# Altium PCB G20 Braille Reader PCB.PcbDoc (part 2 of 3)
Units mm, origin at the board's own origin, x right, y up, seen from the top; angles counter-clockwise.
Board outline 160.1 x 170.2 mm, 2 copper layers (Top Layer, Bottom Layer); 206 components, 272 nets, 975 pads, 345 vias.
Unrouted connection lines stored in the file: 1.
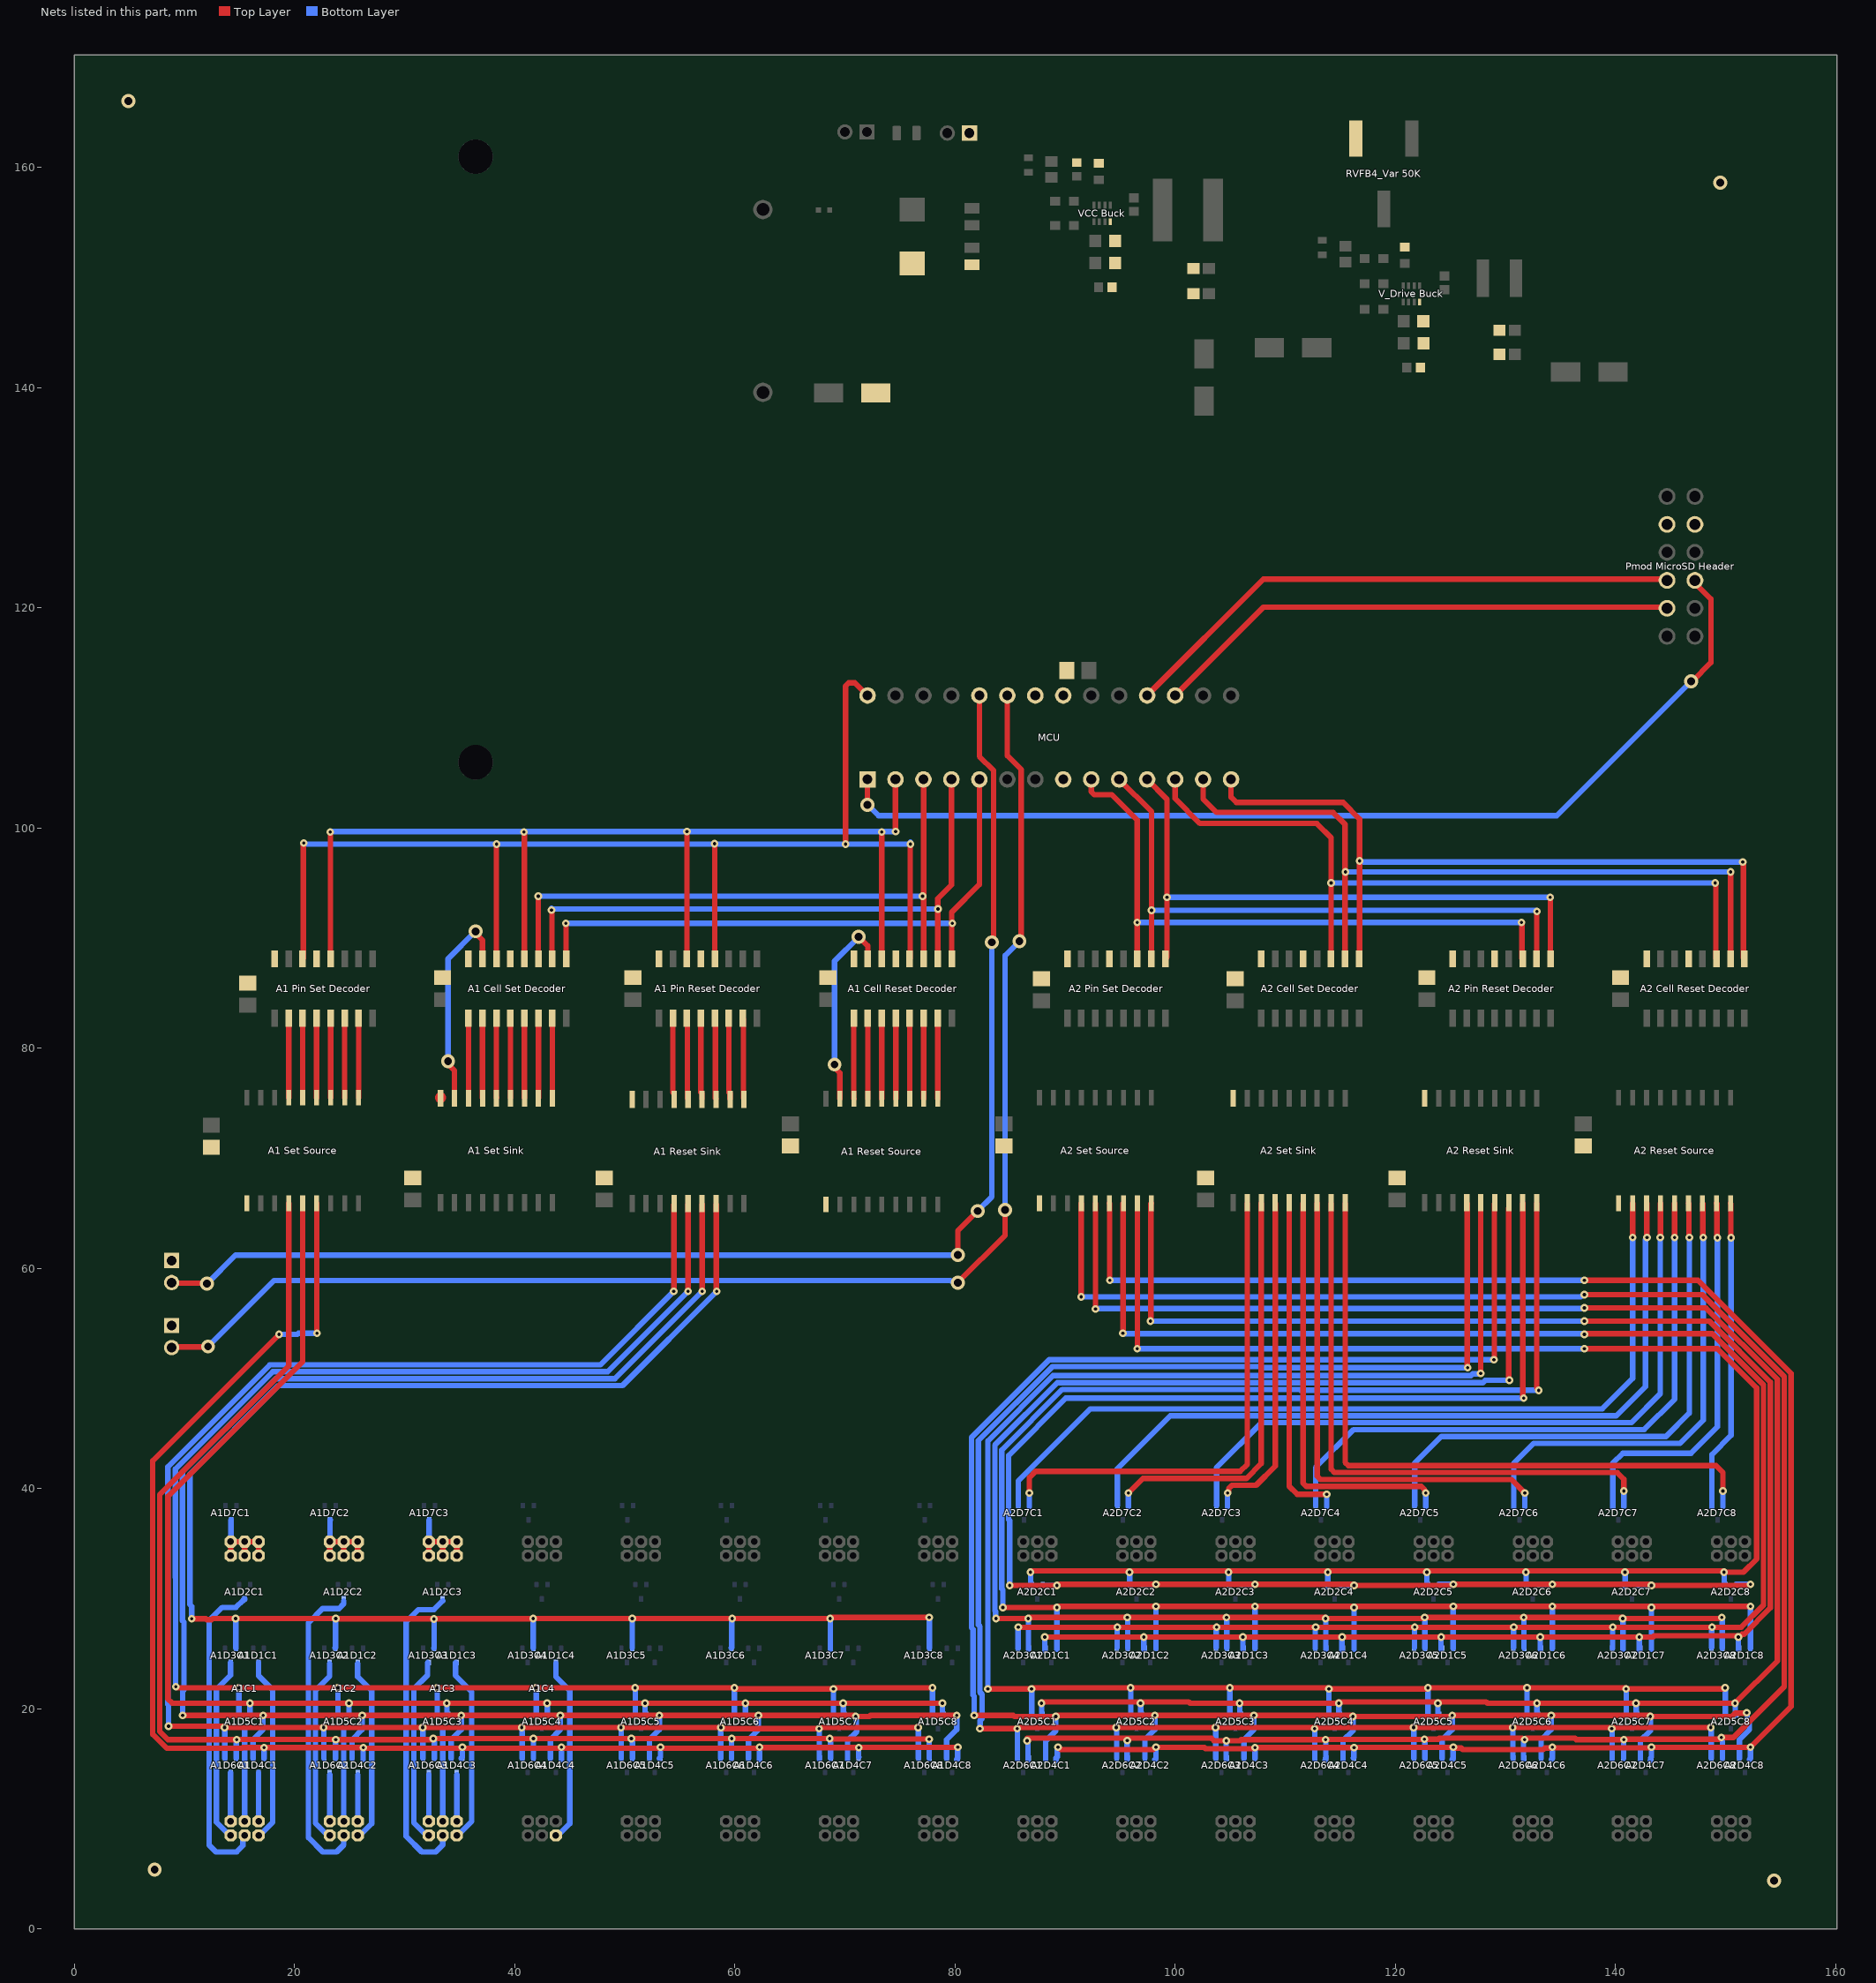
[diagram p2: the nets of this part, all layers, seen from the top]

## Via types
v1: diameter 0.7, hole 0.3, Top Layer to Bottom Layer, 308 vias
v2: diameter 1.27, hole 0.711, Top Layer to Bottom Layer, 37 vias

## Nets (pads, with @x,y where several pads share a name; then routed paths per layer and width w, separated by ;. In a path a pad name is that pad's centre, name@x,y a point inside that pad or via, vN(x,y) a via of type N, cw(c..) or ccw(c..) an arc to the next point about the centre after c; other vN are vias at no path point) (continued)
"A1 Pin3 Reset": "A1 Reset Sink.16" A1D3C1.2 A1D3C2.2 A1D3C3.2 A1D3C4.2 A1D3C5.2 A1D3C6.2 A1D3C7.2 A1D3C8.2 | length 164.7
  Top Layer w0.5: v1(10.673,28.174) 11.953,28.174 12.023,28.105 12.473,28.105 12.573,28.205 v1(14.646,28.205) v1(23.746,28.205) 23.767,28.184 32.65,28.184 v1(32.671,28.163) 32.687,28.18 41.654,28.18 v1(41.671,28.197) v1(50.671,28.197) 50.675,28.201 59.742,28.201 v1(59.746,28.205) 59.75,28.201 68.642,28.201 v1(68.646,28.197) 68.713,28.197 68.821,28.305 v1(77.646,28.305) ; 58.286,65.805 58.316,65.775 58.316,57.935 v1(58.346,57.905)
  Bottom Layer w0.5: v1(10.673,28.174) 10.673,29.298 10.5,29.471 10.5,41.314 18.54,49.354 49.795,49.354 v1(58.346,57.905) ; v1(14.646,28.205) 14.671,28.18 14.671,25.511 A1D3C1.2@14.695,25.487 ; A1D3C2.2@23.695,25.536 23.721,25.561 23.721,28.179 v1(23.746,28.205) ; A1D3C3.2@32.671,25.511 32.683,25.524 32.683,28.151 v1(32.671,28.163) ; A1D3C4.2@41.671,25.511 41.683,25.524 41.683,28.184 v1(41.671,28.197) ; A1D3C5.2@50.671,25.511 50.683,25.524 50.683,28.184 v1(50.671,28.197) ; A1D3C6.2@59.683,25.524 59.721,25.561 59.721,28.179 v1(59.746,28.205) ; v1(68.646,28.197) 68.671,28.172 A1D3C7.2@68.671,25.411 ; A1D3C8.2@77.671,25.511 v1@77.671,28.28
"A1 Pin4": "A1 Set Source.15" A1D4C1.2 A1D4C2.2 A1D4C3.2 A1D4C4.2 A1D4C5.2 A1D4C6.2 A1D4C7.2 A1D4C8.2 | length 138.1
  Top Layer w0.5: v1(17.246,16.479) 15.311,16.479 15.237,16.405 8.409,16.405 7.127,17.686 7.127,42.527 v1(18.6,54) ; v1@17.283,16.442 17.319,16.478 v1(26.246,16.478) ; 22.016,65.905 22.031,65.89 22.031,54.119 v1(22.045,54.105) ; v1@26.246,16.405 35.246,16.405 44.246,16.405 53.246,16.405 62.246,16.405 62.319,16.478 71.223,16.478 v1@71.246,16.455 ; v1@71.246,16.505 v1(80.246,16.505)
  Bottom Layer w0.5: A1D4C1.2@17.241,15.492 17.241,16.473 v1(17.246,16.479) ; v1(18.6,54) 20.251,54 20.356,54.105 v1(22.045,54.105) ; A1D4C2.2@26.241,15.392 26.241,16.472 v1(26.246,16.478) ; A1D4C3.2@35.13,15.494 35.246,15.61 35.241,15.616 35.241,16.399 v1@35.246,16.405 ; A1D4C4.2@44.241,15.392 44.241,16.399 v1@44.246,16.405 ; A1D4C5.2@53.13,15.494 53.246,15.61 53.241,15.616 53.241,16.399 v1@53.246,16.405 ; A1D4C6.2@62.241,15.392 62.241,16.399 v1@62.246,16.405 ; A1D4C7.2@71.246,15.61 71.241,15.616 71.241,16.385 71.246,16.391 v1(71.246,16.478) ; A1D4C8.2@80.141,15.392 80.246,15.498 80.241,15.503 80.241,16.499 v1(80.246,16.505)
  other v1: 35.246,16.505 44.246,16.505 53.246,16.505 62.246,16.505
"A1 Pin4 Reset": "A1 Reset Sink.15" A1D4C1.1 A1D4C2.1 A1D4C3.1 A1D4C4.1 A1D4C5.1 A1D4C6.1 A1D4C7.1 A1D4C8.1 | length 188.9
  Top Layer w0.5: v1(9.846,19.405) v1(35.146,19.405) v1(44.146,19.405) v1(53.146,19.405) 70.819,19.405 70.919,19.305 72.223,19.305 72.323,19.405 v1(80.146,19.405) ; 57.016,65.805 57.024,65.797 57.024,57.913 v1(57.032,57.905)
  Bottom Layer w0.5: v1(9.846,19.405) 9.846,21.596 9.954,21.704 9.954,27.865 9.819,28 9.819,41.519 18.281,49.981 49.108,49.981 v1(57.032,57.905) ; A1D4C1.1@16.235,15.487 16.235,17.194 17.146,18.105 v1(17.146,19.405) ; A1D4C2.1@25.235,15.487 25.235,17.194 26.146,18.105 v1(26.146,19.405) ; A1D4C3.1@34.235,15.487 34.235,17.194 35.146,18.105 v1(35.146,19.405) ; A1D4C4.1@43.235,15.487 43.235,17.194 44.146,18.105 v1(44.146,19.405) ; A1D4C5.1@52.235,15.487 52.235,17.194 53.146,18.105 v1(53.146,19.405) ; A1D4C6.1@61.235,15.487 61.235,17.194 62.146,18.105 v1(62.146,19.405) ; A1D4C7.1@70.235,15.387 70.235,17.094 71.073,17.932 71.073,18.346 71.011,18.408 71.011,19.266 v1(70.973,19.305) ; A1D4C8.1@79.235,15.487 79.235,17.194 80.146,18.105 v1(80.146,19.405)
"A1 Pin5": "A1 Set Source.14" A1D5C1.2 A1D5C2.2 A1D5C3.2 A1D5C4.2 A1D5C5.2 A1D5C6.2 A1D5C7.2 A1D5C8.2 | length 128.6
  Top Layer w0.5: 20.746,65.905 20.746,51.533 8.5,39.287 8.5,20.9 8.895,20.505 v1(15.946,20.505) v1(24.946,20.505) ; v1(24.946,20.505) v1@33.834,20.506 ; v1(33.835,20.506) v1@42.945,20.506 ; v1(42.946,20.505) v1(51.835,20.505) v1(60.946,20.505) v1(69.835,20.505) v1(78.846,20.505)
  Bottom Layer w0.5: v1(15.946,20.505) 15.956,20.495 15.956,19.496 A1D5C1.2@15.965,19.487 ; A1D5C2.2@24.956,19.396 v1@24.956,20.395 ; A1D5C3.2@33.845,19.498 v1@33.845,20.497 ; A1D5C4.2@42.956,19.396 v1@42.956,20.395 ; A1D5C5.2@51.845,19.498 v1@51.845,20.497 ; A1D5C6.2@60.956,19.396 v1@60.956,20.395 ; A1D5C7.2@69.845,19.498 v1@69.845,20.497 ; A1D5C8.2@78.856,19.396 v1@78.856,20.395
"A1 Pin5 Reset": "A1 Reset Sink.14" A1D5C1.1 A1D5C2.1 A1D5C3.1 A1D5C4.1 A1D5C5.1 A1D5C6.1 A1D5C7.1 A1D5C8.1 | length 169
  Top Layer w0.5: v1(9.227,22.005) 9.281,22.005 9.381,21.905 v1(23.946,21.905) v1(32.946,21.905) v1(41.946,21.905) v1(50.946,21.905) v1(59.946,21.905) 60.013,21.905 60.113,21.805 v1(68.946,21.805) 69.013,21.805 69.113,21.905 v1(77.946,21.905) ; v1(55.746,57.905) 55.746,65.805
  Bottom Layer w0.5: v1(9.227,22.005) 9.192,22.04 9.192,31.928 9.184,31.936 9.184,41.771 18.021,50.608 48.449,50.608 v1(55.746,57.905) ; v1(14.946,21.905) 14.956,21.895 14.956,19.496 A1D5C1.1@14.965,19.487 ; A1D5C2.1@23.956,19.496 v1@23.956,21.895 ; A1D5C3.1@32.956,19.496 v1@32.956,21.895 ; A1D5C4.1@41.956,19.496 v1@41.956,21.895 ; A1D5C5.1@50.956,19.496 v1@50.956,21.895 ; A1D5C6.1@59.956,19.496 v1@59.956,21.895 ; A1D5C7.1@68.956,19.396 v1@68.956,21.795 ; A1D5C8.1@77.956,19.496 v1@77.956,21.895
"A1 Pin6": "A1 Set Source.13" A1D6C1.2 A1D6C2.2 A1D6C3.2 A1D6C4.2 A1D6C5.2 A1D6C6.2 A1D6C7.2 A1D6C8.2 | length 137.3
  Top Layer w0.5: 19.476,65.905 19.476,51.149 7.754,39.427 7.754,17.946 8.495,17.205 v1(14.743,17.206) v1(14.743,17.206) v1(23.743,17.205) v1(23.743,17.205) 32.451,17.205 32.546,17.3 v1(68.6,17.3) 68.634,17.266 77.558,17.266 v1@77.619,17.205
  Bottom Layer w0.5: A1D6C1.2@14.719,15.51 14.719,17.182 v1(14.743,17.206) ; A1D6C2.2@23.719,15.51 23.719,17.181 v1(23.743,17.205) ; v1(32.6,17.3) 32.6,17.246 32.695,17.151 A1D6C3.2@32.695,15.51 ; A1D6C4.2@41.702,15.51 41.702,17.294 v1(41.708,17.3) ; v1(50.6,17.3) 50.6,17.246 50.695,17.151 A1D6C5.2@50.695,15.51 ; A1D6C6.2@59.702,15.51 59.702,17.294 v1(59.708,17.3) ; v1(68.6,17.3) 68.6,17.246 68.695,17.151 A1D6C7.2@68.695,15.51 ; A1D6C8.2@77.646,15.51 v1(77.646,17.232)
"A1 Pin6 Reset": "A1 Reset Sink.13" A1D6C1.1 A1D6C2.1 A1D6C3.1 A1D6C4.1 A1D6C5.1 A1D6C6.1 A1D6C7.1 A1D6C8.1 | length 174.5
  Top Layer w0.5: v1(8.551,18.41) 13.474,18.41 13.58,18.305 v1(22.646,18.305) v1(31.646,18.305) v1(40.646,18.305) v1(49.646,18.305) 58.781,18.305 58.881,18.205 v1(67.646,18.205) 67.693,18.252 67.865,18.252 67.918,18.305 v1(76.646,18.305) ; v1(54.446,57.905) 54.461,57.92 54.461,65.79 54.476,65.805
  Bottom Layer w0.5: v1(8.551,18.41) 8.551,20.359 8.5,20.411 8.5,41.974 17.761,51.235 47.776,51.235 v1(54.446,57.905) ; v1(13.646,18.305) 13.671,18.28 13.671,15.511 A1D6C1.1@13.695,15.487 ; A1D6C2.1@22.671,15.511 v1@22.671,18.28 ; A1D6C3.1@31.671,15.511 v1@31.671,18.28 ; A1D6C4.1@40.671,15.511 v1@40.671,18.28 ; A1D6C5.1@49.671,15.511 v1@49.671,18.28 ; A1D6C6.1@58.711,15.51 58.711,18.289 v1(58.727,18.305) ; A1D6C7.1@67.671,15.411 v1@67.671,18.18 ; A1D6C8.1@76.671,15.511 v1@76.671,18.28
"A2 Cell1": "A2 Set Sink.11" A2D7C1.2 | length 46.7
  Top Layer w0.5: v1(86.746,39.605) 86.746,40.997 87.303,41.554 105.895,41.554 106.546,42.205 106.546,59.295 106.536,59.305 106.536,65.905
  Bottom Layer w0.5: A2D7C1.2@86.746,38.35 v1(86.746,39.605)
"A2 Cell1 Reset": "A2 Reset Source.11" A2D7C1.1 | length 77.8
  Top Layer w0.5: 141.536,65.905 141.541,65.9 141.541,62.81 v1(141.546,62.805)
  Bottom Layer w0.5: A2D7C1.1@85.746,38.45 85.746,40.705 92.276,47.235 138.776,47.235 141.541,50 141.541,62.8 v1(141.546,62.805)
"A2 Cell2": "A2 Set Sink.12" A2D7C2.2 | length 38.1
  Top Layer w0.5: v1(95.746,39.605) 97.068,40.927 106.468,40.927 107.806,42.265 107.806,65.905
  Bottom Layer w0.5: A2D7C2.2@95.746,38.35 v1(95.746,39.605)
"A2 Cell2 Reset": "A2 Reset Source.12" A2D7C2.1 | length 71.1
  Top Layer w0.5: 142.806,65.905 142.826,65.885 142.826,62.825 v1(142.846,62.805)
  Bottom Layer w0.5: A2D7C2.1@94.746,38.45 94.746,41.805 99.549,46.608 140.049,46.608 142.7,49.259 142.7,62.605 142.846,62.751 v1(142.846,62.805)
"A2 Cell3": "A2 Set Sink.13" A2D7C3.2 | length 30.6
  Top Layer w0.5: v1@104.793,39.652 104.784,39.661 104.784,39.697 104.846,39.759 104.846,40.007 105.139,40.3 107.341,40.3 109.076,42.035 109.076,65.905
  Bottom Layer w0.5: A2D7C3.2@104.746,38.35 v1(104.746,39.605)
"A2 Cell3 Reset": "A2 Reset Source.13" A2D7C3.1 | length 63.8
  Top Layer w0.5: v1(144.046,62.805) 144.061,62.82 144.061,65.89 144.076,65.905
  Bottom Layer w0.5: A2D7C3.1@103.746,38.455 103.746,41.905 107.822,45.981 141.422,45.981 144.046,48.605 v1(144.046,62.805)
"A2 Cell4": "A2 Set Sink.14" A2D7C4.2 | length 30.5
  Top Layer w0.5: 110.346,65.905 110.346,40.205 111.078,39.473 v1(113.746,39.473)
  Bottom Layer w0.5: A2D7C4.2@113.746,38.35 v1(113.746,39.473)
"A2 Cell4 Reset": "A2 Reset Source.14" A2D7C4.1 | length 56.4
  Top Layer w0.5: v1(145.346,62.805) 145.346,65.905
  Bottom Layer w0.5: A2D7C4.1@112.746,38.45 112.746,41.905 116.195,45.354 142.595,45.354 145.346,48.105 v1(145.346,62.805)
"A2 Cell5": "A2 Set Sink.15" A2D7C5.2 | length 38.2
  Top Layer w0.5: 111.616,65.905 111.616,40.493 111.909,40.2 122.353,40.2 122.646,39.907 122.646,39.759 122.708,39.697 122.708,39.661 v1@122.699,39.652
  Bottom Layer w0.5: A2D7C5.2@122.746,38.35 v1(122.746,39.605)
"A2 Cell5 Reset": "A2 Reset Source.15" A2D7C5.1 | length 49.8
  Top Layer w0.5: 146.616,65.905 146.652,65.869 146.652,62.84 v1(146.687,62.805)
  Bottom Layer w0.5: A2D7C5.1@121.746,38.45 121.746,42.305 124.168,44.727 144.568,44.727 146.687,46.846 v1(146.687,62.805)
"A2 Cell6": "A2 Set Sink.16" A2D7C6.2 | length 45.5
  Top Layer w0.5: 112.886,65.905 112.886,41.12 113.179,40.827 130.524,40.827 v1(131.746,39.605)
  Bottom Layer w0.5: A2D7C6.2@131.746,38.35 v1(131.746,39.605)
"A2 Cell6 Reset": "A2 Reset Source.16" A2D7C6.1 | length 42.6
  Top Layer w0.5: 147.886,65.905 147.916,65.875 147.916,62.835 v1(147.946,62.805)
  Bottom Layer w0.5: A2D7C6.1@130.746,38.25 A2D7C6.1@130.746,38.45 130.746,42.305 132.541,44.1 145.841,44.1 147.946,46.205 v1(147.946,62.805)
"A2 Cell7": "A2 Set Sink.17" A2D7C7.2 | length 53.6
  Top Layer w0.5: 114.156,65.905 114.156,41.747 114.449,41.454 140.148,41.454 140.746,40.856 v1(140.746,39.774)
  Bottom Layer w0.5: A2D7C7.2@140.746,38.35 v1(140.746,39.774)
"A2 Cell7 Reset": "A2 Reset Source.17" A2D7C7.1 | length 35.3
  Top Layer w0.5: 149.156,65.905 149.201,65.86 149.201,62.819 v1(149.246,62.774)
  Bottom Layer w0.5: A2D7C7.1@139.746,38.25 A2D7C7.1@139.746,38.45 139.746,42.305 140.646,43.205 146.846,43.205 149.246,45.605 v1(149.246,62.774)
"A2 Cell8": "A2 Set Sink.18" A2D7C8.2 | length 61.3
  Top Layer w0.5: 115.426,65.905 115.426,42.374 115.719,42.081 149.121,42.081 149.746,41.456 v1(149.746,39.774)
  Bottom Layer w0.5: A2D7C8.2@149.746,38.35 v1(149.746,39.774)
"A2 Cell8 Reset": "A2 Reset Source.18" A2D7C8.1 | length 28.4
  Top Layer w0.5: 150.426,65.905 150.457,65.874 150.457,62.804 v1(150.487,62.774)
  Bottom Layer w0.5: A2D7C8.1@148.746,38.25 A2D7C8.1@148.746,38.45 148.746,43.096 150.487,44.837 v1(150.487,62.774)
"A2 Cell Select 0": "A2 Cell Reset Decoder.1" "A2 Cell Set Decoder.1" MCU.14 | length 70.5
  Top Layer w0.5: MCU.14@105.066,104.405 105.066,102.785 105.546,102.305 115.246,102.305 116.746,100.805 v1(116.746,97.005) 116.746,88.16 116.691,88.105 ; v1(151.546,96.905) 151.593,96.858 151.593,88.208 151.696,88.105
  Bottom Layer w0.5: v1(116.746,97.005) 116.8,97.005 116.9,96.905 v1(151.546,96.905)
"A2 Cell Select 1": "A2 Cell Reset Decoder.2" "A2 Cell Set Decoder.2" MCU.13 | length 70.8
  Top Layer w0.5: MCU.13@102.526,104.405 102.526,102.625 103.746,101.405 114.346,101.405 115.421,100.33 115.421,88.105 ; 150.426,88.105 150.436,88.115 150.436,95.995 v1(150.446,96.005)
  Bottom Layer w0.5: v1(115.446,96.005) v1(150.446,96.005)
"A2 Cell Select 2": "A2 Cell Reset Decoder.3" "A2 Cell Set Decoder.3" MCU.12 | length 70.2
  Top Layer w0.5: MCU.12@99.986,104.405 99.986,102.665 102.246,100.405 112.846,100.405 114.151,99.1 114.151,88.105 ; v1(149.046,95.005) 149.093,94.958 149.093,88.168 149.156,88.105
  Bottom Layer w0.5: v1(114.146,95.005) v1(149.046,95.005)
"A2 Pin1": "A2 Set Source.18" A2D1C1.1 A2D1C2.1 A2D1C3.1 A2D1C4.1 A2D1C5.1 A2D1C6.1 A2D1C7.1 A2D1C8.1 | length 165.3
  Top Layer w0.5: v1@88.213,26.528 88.236,26.505 97.054,26.505 97.146,26.597 97.238,26.505 106.19,26.505 106.233,26.548 106.233,26.51 106.238,26.505 115.19,26.505 115.233,26.548 115.233,26.51 115.238,26.505 124.054,26.505 124.146,26.597 124.238,26.505 133.19,26.505 133.233,26.548 133.233,26.51 133.238,26.505 142.19,26.505 142.233,26.548 142.233,26.51 142.238,26.505 143.373,26.505 143.496,26.628 v1@151.146,26.628 ; v1(97.746,55.205) 97.786,55.245 97.786,65.865 97.826,65.905 ; v1(137.146,55.205) 148.519,55.205 154.054,49.67 154.054,29.167 151.664,26.778 151.473,26.778 151.2,26.505 v1(151.146,26.505)
  Bottom Layer w0.5: A2D1C1.1@88.141,25.292 v1@88.141,26.299 ; A2D1C2.1@97.141,25.392 v1@97.141,26.399 ; v1(97.746,55.205) v1(137.146,55.205) ; A2D1C3.1@106.141,25.392 v1@106.141,26.399 ; A2D1C4.1@115.141,25.292 v1@115.141,26.299 ; A2D1C5.1@124.141,25.392 v1@124.141,26.399 ; A2D1C6.1@133.141,25.392 v1@133.141,26.399 ; A2D1C7.1@142.141,25.292 v1@142.141,26.299 ; A2D1C8.1@151.141,25.392 v1@151.141,26.399
  other v1: 88.146,26.505 97.146,26.505 106.146,26.505 115.146,26.505 124.146,26.505 133.146,26.505 142.146,26.505
"A2 Pin1 Reset": "A2 Reset Sink.18" A2D1C1.2 A2D1C2.2 A2D1C3.2 A2D1C4.2 A2D1C5.2 A2D1C6.2 A2D1C7.2 A2D1C8.2 | length 180.9
  Top Layer w0.5: v1@84.335,29.205 89.312,29.205 89.413,29.305 v1(98.246,29.305) v1(107.246,29.305) 116.246,29.305 v1(125.246,29.305) v1(134.246,29.305) 143.246,29.305 v1(152.246,29.305) ; 132.826,65.905 132.826,49.15 133.005,48.971 v1(133.005,48.905)
  Bottom Layer w0.5: v1(84.335,29.205) 84.335,30.804 84.235,30.904 84.235,43.494 89.738,48.997 111.298,48.997 111.363,48.932 132.978,48.932 v1(133.005,48.905) ; A2D1C1.2@89.241,25.392 v1@89.241,29.199 ; A2D1C2.2@98.241,25.492 v1@98.241,29.299 ; A2D1C3.2@107.241,25.492 v1@107.241,29.299 ; A2D1C4.2@116.241,25.392 v1@116.241,29.199 ; A2D1C5.2@125.241,25.492 v1@125.241,29.299 ; A2D1C6.2@134.241,25.492 v1@134.241,29.299 ; A2D1C7.2@143.241,25.392 v1@143.241,29.199 ; A2D1C8.2@152.241,25.492 v1@152.241,29.299
  other v1: 89.246,29.205 116.246,29.205 143.246,29.205
"A2 Pin2": "A2 Set Source.17" A2D2C1.1 A2D2C2.1 A2D2C3.1 A2D2C4.1 A2D2C5.1 A2D2C6.1 A2D2C7.1 A2D2C8.1 | length 162
  Top Layer w0.5: v1@86.846,32.528 v1@95.68,32.528 ; v1@95.68,32.428 95.78,32.528 113.68,32.528 v1@113.78,32.428 ; v1(96.546,52.705) 96.551,52.71 96.551,65.9 96.556,65.905 ; v1@113.78,32.528 v1@122.68,32.528 ; v1@122.68,32.428 122.78,32.528 140.68,32.528 v1@140.78,32.428 ; v1(137.146,52.705) 149.246,52.705 152.8,49.151 152.8,33.597 151.608,32.405 v1(149.846,32.405) ; v1@140.78,32.528 v1@149.68,32.528 ; v1@149.68,32.428 149.78,32.528 v1@149.846,32.528
  Bottom Layer w0.5: A2D2C1.1@86.856,31.093 v1@86.856,32.195 ; A2D2C2.1@95.856,31.193 v1@95.856,32.295 ; v1(96.546,52.705) v1(137.146,52.705) ; A2D2C3.1@104.856,31.193 v1@104.856,32.295 ; A2D2C4.1@113.856,31.093 v1@113.856,32.195 ; A2D2C5.1@122.856,31.193 v1@122.856,32.295 ; A2D2C6.1@131.856,31.193 v1@131.856,32.295 ; A2D2C7.1@140.856,31.093 v1@140.856,32.195 ; A2D2C8.1@149.856,31.193 v1@149.856,32.295
  other v1: 86.846,32.405 95.846,32.405 104.846,32.405 113.846,32.405 122.846,32.405 131.846,32.405 140.846,32.405
"A2 Pin2 Reset": "A2 Reset Sink.17" A2D2C1.2 A2D2C2.2 A2D2C3.2 A2D2C4.2 A2D2C5.2 A2D2C6.2 A2D2C7.2 A2D2C8.2 | length 156.2
  Top Layer w0.5: v1(84.962,31.205) 89.313,31.205 89.413,31.305 v1(98.246,31.305) 116.092,31.305 116.154,31.243 116.192,31.243 116.246,31.297 116.338,31.205 125.092,31.205 125.192,31.305 143.092,31.305 143.154,31.243 143.192,31.243 143.246,31.297 143.338,31.205 152.092,31.205 152.192,31.305 v1(152.246,31.305) ; 131.556,65.905 131.556,48.361 131.646,48.271 v1(131.646,48.205)
  Bottom Layer w0.5: v1(84.962,31.205) 84.962,37.09 84.862,37.19 84.862,43.021 90.046,48.205 v1(131.646,48.205) ; A2D2C1.2@87.976,31.194 v1@89.236,31.194 ; A2D2C2.2@96.976,31.294 v1@98.236,31.294 ; A2D2C3.2@105.976,31.294 v1@107.236,31.294 ; A2D2C4.2@114.976,31.194 v1@116.236,31.194 ; A2D2C5.2@123.976,31.294 v1@125.236,31.294 ; A2D2C6.2@132.976,31.294 v1@134.236,31.294 ; A2D2C7.2@141.976,31.194 v1@143.236,31.194 ; A2D2C8.2@150.976,31.294 v1@152.236,31.294
  other v1: 89.246,31.205 116.246,31.205 143.246,31.205 107.246,31.305 125.246,31.305 134.246,31.305
"A2 Pin3": "A2 Set Source.16" A2D3C1.1 A2D3C2.1 A2D3C3.1 A2D3C4.1 A2D3C5.1 A2D3C6.1 A2D3C7.1 A2D3C8.1 | length 175.3
  Top Layer w0.5: v1(85.746,27.405) 94.654,27.405 94.708,27.459 94.708,27.497 94.8,27.405 103.654,27.405 103.746,27.497 103.838,27.405 112.657,27.405 v1@112.68,27.428 ; v1(95.246,54.105) 95.266,54.125 95.266,65.885 95.286,65.905 ; v1(112.746,27.405) 121.654,27.405 121.746,27.497 121.838,27.405 130.654,27.405 130.746,27.497 130.838,27.405 139.657,27.405 v1@139.68,27.428 ; v1(137.146,54.005) 137.205,54.063 148.774,54.063 153.427,49.411 153.427,29.427 151.405,27.405 v1(148.746,27.405) ; v1(139.746,27.405) 148.654,27.405 v1@148.746,27.497
  Bottom Layer w0.5: A2D3C1.1@85.721,25.463 v1@85.721,27.279 ; A2D3C2.1@94.721,25.563 v1@94.721,27.379 ; v1(95.246,54.105) 95.296,54.055 137.096,54.055 v1(137.146,54.005) ; A2D3C3.1@103.721,25.563 v1@103.721,27.379 ; A2D3C4.1@112.721,25.463 v1@112.721,27.279 ; A2D3C5.1@121.721,25.563 v1@121.721,27.379 ; A2D3C6.1@130.721,25.563 v1@130.721,27.379 ; A2D3C7.1@139.721,25.463 v1@139.721,27.279 ; A2D3C8.1@148.721,25.563 v1@148.721,27.379
  other v1: 94.746,27.405 103.746,27.405 121.746,27.405 130.746,27.405
"A2 Pin3 Reset": "A2 Reset Sink.16" A2D3C1.2 A2D3C2.2 A2D3C3.2 A2D3C4.2 A2D3C5.2 A2D3C6.2 A2D3C7.2 A2D3C8.2 | length 169
  Top Layer w0.5: v1(83.708,28.205) 86.713,28.205 86.813,28.305 v1(95.646,28.305) 113.492,28.305 113.554,28.243 113.592,28.243 113.646,28.297 113.738,28.205 122.492,28.205 122.592,28.305 140.492,28.305 140.554,28.243 140.592,28.243 140.646,28.297 140.738,28.205 149.492,28.205 149.592,28.305 v1(149.646,28.305) ; 130.286,65.437 130.286,49.941 130.346,49.881 v1(130.346,49.827)
  Bottom Layer w0.5: v1(83.708,28.205) 83.67,28.243 83.67,28.843 83.608,28.904 83.608,43.944 89.288,49.624 127.944,49.624 128.147,49.827 v1(130.346,49.827) ; A2D3C1.2@86.671,25.411 v1@86.671,28.18 ; A2D3C2.2@95.671,25.511 v1@95.671,28.28 ; A2D3C3.2@104.671,25.511 v1@104.671,28.28 ; A2D3C4.2@113.671,25.411 v1@113.671,28.18 ; A2D3C5.2@122.671,25.511 v1@122.671,28.28 ; A2D3C6.2@131.671,25.511 v1@131.671,28.28 ; A2D3C7.2@140.671,25.411 v1@140.671,28.18 ; A2D3C8.2@149.671,25.511 v1@149.671,28.28
  other v1: 86.646,28.205 113.646,28.205 140.646,28.205 104.646,28.305 122.646,28.305 131.646,28.305
"A2 Pin4": "A2 Set Source.15" A2D4C1.2 A2D4C2.2 A2D4C3.2 A2D4C4.2 A2D4C5.2 A2D4C6.2 A2D4C7.2 A2D4C8.2 | length 180.4
  Top Layer w0.5: v1(89.346,16.505) 89.4,16.505 89.605,16.3 97.987,16.3 98.192,16.505 102.633,16.505 102.76,16.378 107.092,16.378 107.192,16.478 v1(116.246,16.478) ; 94.016,65.905 94.031,65.89 94.031,58.92 v1(94.046,58.905) ; v1@116.273,16.505 v1(125.246,16.505) 125.319,16.432 125.977,16.432 126.104,16.305 133.438,16.305 133.572,16.439 134.18,16.439 v1(134.246,16.505) 134.3,16.451 143.192,16.451 v1(143.246,16.505) v1(152.246,16.505) 155.935,20.194 155.935,50.449 147.48,58.905 v1(137.146,58.905)
  Bottom Layer w0.5: A2D4C1.2@89.141,15.292 89.162,15.314 89.162,15.526 89.246,15.61 89.268,15.61 89.291,15.633 89.291,16.449 v1(89.346,16.505) ; v1(94.046,58.905) v1(137.146,58.905) ; A2D4C2.2@98.141,15.392 98.246,15.498 98.241,15.503 98.241,16.499 v1(98.246,16.505) ; A2D4C3.2@107.241,15.51 107.241,16.472 v1(107.246,16.478) ; A2D4C4.2@116.162,15.526 116.208,15.572 116.208,16.439 v1(116.246,16.478) ; A2D4C5.2@125.141,15.392 125.246,15.498 125.241,15.503 125.241,16.499 v1(125.246,16.505) ; A2D4C6.2@134.141,15.392 134.246,15.498 134.241,15.503 134.241,16.499 v1(134.246,16.505) ; A2D4C7.2@143.141,15.292 143.162,15.314 143.162,15.526 143.246,15.61 143.241,15.616 143.241,16.499 v1(143.246,16.505) ; A2D4C8.2@152.141,15.392 152.246,15.498 152.241,15.503 152.241,16.499 v1(152.246,16.505)
"A2 Pin4 Reset": "A2 Reset Sink.15" A2D4C1.1 A2D4C2.1 A2D4C3.1 A2D4C4.1 A2D4C5.1 A2D4C6.1 A2D4C7.1 A2D4C8.1 | length 195.2
  Top Layer w0.5: v1(81.727,19.405) 85.273,19.405 85.373,19.305 89.213,19.305 89.313,19.405 v1(98.146,19.405) v1(107.146,19.405) 115.98,19.405 116.032,19.352 116.093,19.352 116.146,19.405 116.16,19.405 116.26,19.305 124.98,19.305 125.08,19.405 v1(134.146,19.405) 142.98,19.405 143.032,19.352 143.093,19.352 143.146,19.405 143.16,19.405 143.26,19.305 150.561,19.305 150.858,19.601 151.873,19.601 v1(151.911,19.639) ; v1(128.946,51.705) 128.981,51.74 128.981,65.87 129.016,65.905
  Bottom Layer w0.5: v1(81.727,19.405) 81.727,21.144 81.627,21.244 81.627,27.222 81.492,27.357 81.492,44.651 88.546,51.705 v1(128.946,51.705) ; A2D4C1.1@88.235,15.387 88.235,17.094 89.146,18.005 v1(89.146,19.305) ; A2D4C2.1@97.235,15.487 A2D4C2.1@97.235,15.505 97.235,17.194 98.146,18.105 v1(98.146,19.405) ; A2D4C3.1@106.235,15.487 A2D4C3.1@106.235,15.505 106.235,17.194 107.146,18.105 v1(107.146,19.405) ; A2D4C4.1@115.235,15.387 A2D4C4.1@115.235,15.505 115.235,17.094 116.146,18.005 v1(116.146,19.305) ; A2D4C5.1@124.235,15.487 A2D4C5.1@124.235,15.505 124.235,17.194 125.146,18.105 v1(125.146,19.405) ; A2D4C6.1@133.235,15.487 A2D4C6.1@133.235,15.505 133.235,17.194 134.146,18.105 v1(134.146,19.405) ; A2D4C7.1@142.235,15.387 A2D4C7.1@142.235,15.505 142.235,17.094 143.146,18.005 v1(143.146,19.305) ; A2D4C8.1@151.235,15.505 151.235,17.194 152.146,18.105 152.146,18.789 151.95,18.986 151.95,19.601 v1(151.911,19.639)
"A2 Pin5": "A2 Set Source.14" A2D5C1.2 A2D5C2.2 A2D5C3.2 A2D5C4.2 A2D5C5.2 A2D5C6.2 A2D5C7.2 A2D5C8.2 | length 176.6
  Top Layer w0.5: v1@87.846,20.628 v1@96.68,20.628 ; v1(92.746,56.305) 92.746,65.905 ; v1@96.73,20.578 96.78,20.628 101.218,20.628 101.341,20.505 105.732,20.505 105.846,20.618 105.96,20.505 114.757,20.505 v1@114.78,20.528 ; v1@114.78,20.628 v1@123.68,20.628 ; v1@123.73,20.578 123.78,20.628 128.218,20.628 128.341,20.505 132.732,20.505 132.846,20.618 132.96,20.505 141.732,20.505 141.824,20.596 141.824,20.605 141.924,20.505 150.732,20.505 v1@150.846,20.618 ; v1(137.146,56.405) 148.206,56.405 154.681,49.93 154.681,24.34 v1(150.846,20.505)
  Bottom Layer w0.5: A2D5C1.2@87.856,19.296 v1@87.856,20.295 ; v1(92.746,56.305) 92.796,56.355 137.096,56.355 v1(137.146,56.405) ; A2D5C2.2@96.856,19.396 v1@96.856,20.395 ; A2D5C3.2@105.856,19.396 v1@105.856,20.395 ; A2D5C4.2@114.856,19.296 v1@114.856,20.295 ; A2D5C5.2@123.856,19.396 v1@123.856,20.395 ; A2D5C6.2@132.856,19.396 v1@132.856,20.395 ; A2D5C7.2@141.856,19.296 v1@141.856,20.295 ; A2D5C8.2@150.856,19.396 v1@150.856,20.395
  other v1: 87.846,20.505 96.846,20.505 105.846,20.505 114.846,20.505 123.846,20.505 132.846,20.505 141.846,20.505
"A2 Pin5 Reset": "A2 Reset Sink.14" A2D5C1.1 A2D5C2.1 A2D5C3.1 A2D5C4.1 A2D5C5.1 A2D5C6.1 A2D5C7.1 A2D5C8.1 | length 171.3
  Top Layer w0.5: v1(82.981,21.805) 87.013,21.805 87.113,21.905 v1(95.946,21.905) 113.792,21.905 113.854,21.843 113.892,21.843 113.946,21.897 114.038,21.805 122.792,21.805 122.892,21.905 140.792,21.905 140.854,21.843 140.892,21.843 140.946,21.897 141.038,21.805 149.792,21.805 149.892,21.905 v1(149.946,21.905) ; v1(127.746,50.454) 127.746,65.437
  Bottom Layer w0.5: v1(82.981,21.805) 82.981,44.34 88.892,50.251 126.847,50.251 127.012,50.416 127.708,50.416 v1(127.746,50.454) ; A2D5C1.1@86.956,19.396 v1@86.956,21.795 ; A2D5C2.1@95.956,19.496 v1@95.956,21.895 ; A2D5C3.1@104.956,19.496 v1@104.956,21.895 ; A2D5C4.1@113.956,19.396 v1@113.956,21.795 ; A2D5C5.1@122.956,19.496 v1@122.956,21.895 ; A2D5C6.1@131.956,19.496 v1@131.956,21.895 ; A2D5C7.1@140.956,19.396 v1@140.956,21.795 ; A2D5C8.1@149.956,19.496 v1@149.956,21.895
  other v1: 86.946,21.805 113.946,21.805 140.946,21.805 104.946,21.905 122.946,21.905 131.946,21.905
"A2 Pin6": "A2 Set Source.13" A2D6C1.2 A2D6C2.2 A2D6C3.2 A2D6C4.2 A2D6C5.2 A2D6C6.2 A2D6C7.2 A2D6C8.2 | length 189.2
  Top Layer w0.5: v1@86.535,17.328 v1@95.635,17.328 ; v1(91.446,57.405) 91.461,57.42 91.461,65.89 91.476,65.905 ; v1(95.635,17.109) v1@95.635,17.328 ; v1(104.635,17.105) 105.885,17.105 105.985,17.205 v1(113.646,17.205) 113.66,17.218 122.572,17.218 v1@122.635,17.155 ; v1@104.635,17.19 104.55,17.105 103.508,17.105 103.285,17.328 v1@95.635,17.328 ; v1(122.635,17.232) 123.889,17.232 123.985,17.328 131.491,17.328 131.529,17.29 v1@131.764,17.29 ; v1(131.735,17.205) v1@131.858,17.328 ; v1@131.8,17.27 131.827,17.243 131.912,17.328 136.291,17.328 136.414,17.205 v1(140.743,17.205) ; v1(137.146,57.605) 147.893,57.605 155.308,50.19 155.308,22.008 150.7,17.4 149.546,17.4 149.378,17.232 140.773,17.232 v1@140.746,17.205
  Bottom Layer w0.5: A2D6C1.2@86.621,15.312 v1@86.621,16.979 ; v1(91.446,57.405) 136.825,57.405 137.025,57.605 v1(137.146,57.605) ; A2D6C2.2@95.621,15.412 95.621,17.094 v1(95.635,17.109) ; A2D6C3.2@104.621,15.412 v1@104.621,17.079 ; A2D6C4.2@113.621,15.312 113.622,15.314 113.622,15.506 113.671,15.555 113.671,17.18 v1(113.646,17.205) ; v1(122.635,17.232) 122.665,17.202 A2D6C5.2@122.665,15.51 ; A2D6C6.2@131.621,15.412 v1@131.621,17.079 ; A2D6C7.2@140.719,15.51 140.719,17.181 v1(140.743,17.205) ; v1(149.6,17.4) 149.6,17.346 149.695,17.251 A2D6C8.2@149.695,15.51
  other v1: 86.535,17.105
"A2 Pin6 Reset": "A2 Reset Sink.13" A2D6C1.1 A2D6C2.1 A2D6C3.1 A2D6C4.1 A2D6C5.1 A2D6C6.1 A2D6C7.1 A2D6C8.1 | length 177.2
  Top Layer w0.5: v1(82.246,18.205) 85.713,18.205 85.813,18.305 v1(94.646,18.305) v1(103.646,18.305) v1(121.646,18.305) v1(130.646,18.305) v1(148.646,18.305) ; 126.476,65.905 126.511,65.87 126.511,51.013 v1(126.546,50.978)
  Bottom Layer w0.5: v1(82.246,18.205) 82.284,18.243 82.284,18.934 82.454,19.104 82.454,21.304 82.254,21.504 82.254,27.482 82.119,27.617 82.119,44.364 88.832,51.078 107.612,51.078 107.712,50.978 v1(126.546,50.978) ; A2D6C1.1@85.671,15.411 v1@85.671,18.18 ; A2D6C2.1@94.671,15.511 v1@94.671,18.28 ; A2D6C3.1@103.671,15.511 v1@103.671,18.28 ; A2D6C4.1@112.671,15.411 v1@112.671,18.18 ; A2D6C5.1@121.671,15.511 v1@121.671,18.28 ; A2D6C6.1@130.671,15.511 v1@130.671,18.28 ; A2D6C7.1@139.671,15.411 v1@139.671,18.18 ; A2D6C8.1@148.671,15.511 v1@148.671,18.28
  other v1: 85.646,18.205 112.646,18.205 139.646,18.205
"A2 Pin Select 0": "A2 Pin Reset Decoder.1" "A2 Pin Set Decoder.1" MCU.11 | length 57.6
  Top Layer w0.5: MCU.11@97.446,104.405 99.246,102.605 v1(99.246,93.705) 99.246,88.26 99.091,88.105 ; v1(134.046,93.705) 134.069,93.682 134.069,88.127 134.091,88.105
  Bottom Layer w0.5: v1(99.246,93.705) v1@134.146,93.705
"A2 Pin Select 1": "A2 Pin Reset Decoder.2" "A2 Pin Set Decoder.2" MCU.10 | length 56.9
  Top Layer w0.5: MCU.10@94.906,104.405 97.846,101.465 97.846,92.53 97.821,92.505 97.834,92.492 97.834,88.117 97.821,88.105 ; 132.821,88.105 132.834,88.117 132.834,92.392 v1(132.846,92.405)
  Bottom Layer w0.5: v1(97.846,92.505) 132.746,92.505 v1(132.846,92.405)
"A2 Pin Select 2": "A2 Pin Reset Decoder.3" "A2 Pin Set Decoder.3" MCU.9 | length 57.3
  Top Layer w0.5: MCU.9@92.366,104.405 92.366,103.285 92.646,103.005 94.246,103.005 94.686,102.565 96.546,100.705 v1(96.546,91.405) 96.546,88.11 96.551,88.105 ; v1(131.446,91.405) 131.493,91.358 131.493,88.163 131.551,88.105
  Bottom Layer w0.5: v1(96.546,91.405) 131.246,91.405 v1@131.446,91.205
CD: "Pmod MicroSD Header.9" MCU.1 | length 93.4
  Top Layer w0.5: v2(72.046,102.105) MCU.1@72.046,104.405 ; v2(146.846,113.305) 146.946,113.305 148.646,115.005 148.646,120.785 146.846,122.585
  Bottom Layer w0.5: v2(72.046,102.105) 73.046,101.105 134.646,101.105 v2(146.846,113.305)
"Cell Select 0": "A1 Cell Reset Decoder.1" "A1 Cell Set Decoder.1" MCU.5 | length 55.7
  Top Layer w0.5: v1(44.649,91.329) 44.67,91.308 44.67,88.126 44.691,88.105 ; 79.691,88.105 79.691,92.35 82.206,94.865 MCU.5@82.206,104.405
  Bottom Layer w0.5: v1@44.671,91.329 v1(79.749,91.329)
"Cell Select 1": "A1 Cell Reset Decoder.2" "A1 Cell Set Decoder.2" MCU.4 | length 56.4
  Top Layer w0.5: v1(43.349,92.529) 43.385,92.493 43.385,88.141 43.421,88.105 ; 78.421,88.105 78.421,93.58 79.666,94.825 MCU.4@79.666,104.405
  Bottom Layer w0.5: v1@43.346,92.705 43.421,92.629 v1(78.449,92.629)
"Cell Select 2": "A1 Cell Reset Decoder.3" "A1 Cell Set Decoder.3" MCU.3 | length 57
  Top Layer w0.5: v1(42.146,93.805) 42.149,93.802 42.149,88.107 42.151,88.105 ; MCU.3@77.126,104.405 77.139,104.392 77.139,93.964 77.046,93.871 77.046,93.738 77.139,93.646 77.139,88.117 77.151,88.105
  Bottom Layer w0.5: v1(42.146,93.805) v1(77.046,93.805)
GND: "A1 Cell Reset Decoder.5" "A1 Cell Reset Decoder.8" "A1 Cell Set Decoder.5" "A1 Cell Set Decoder.8" "A1 Pin Reset Decoder.5" "A1 Pin Reset Decoder.8" "A1 Pin Set Decoder.5" "A1 Pin Set Decoder.8" "A1 Reset Sink.9" "A1 Reset Source.10" "A1 Set Sink.9" "A1 Set Source.10" "A2 Cell Reset Decoder.5" "A2 Cell Reset Decoder.8" "A2 Cell Set Decoder.5" "A2 Cell Set Decoder.8" "A2 Pin Reset Decoder.5" "A2 Pin Reset Decoder.8" "A2 Pin Set Decoder.5" "A2 Pin Set Decoder.8" "A2 Reset Sink.9" "A2 Reset Source.10" "A2 Set Sink.9" "A2 Set Source.10" "Back Button.1" "Forward Button.1" "Pmod MicroSD Header.5" "Pmod MicroSD Header.11" "RVFB4_Var 50K.3" "V_Drive Buck.4" "VCC Buck.4" C1_D.2 C1_MCU.1 C2_D.2 C3_D.2 C4_D.2 C5_D.1 C6_D.1 C7_D.1 C8_D.1 C9_D.2 C10_D.2 C11_D.2 C12_D.2 C13_D.1 C14_D.1 C15_D.1 C16_D.1 Cin1.1 Cin2.1 Cin3.2 Cin4.1 Cin5.1 Cin6.2 Cout1.2 Cout2.2 Cout3.2 Cout4.2 CSS1.2 CSS2.2 LED.1 MCU.8 MCU.21 MCU.22 RDown_EN.1 RFB2.1 SKD.1 TVS.1 | length 0
  other v2: 154.4,4.4 7.3,5.4 149.5,158.6 4.9,166
"Input Back": "Back Button.2" MCU.24 | length 125.2
  Top Layer w0.5: 8.846,58.705 8.896,58.655 11.996,58.655 v2(12.046,58.605) ; v2(80.246,61.205) 80.246,63.405 v2(82.046,65.205) ; MCU.24@82.206,112.025 82.206,106.494 83.5,105.2 83.5,89.759 v2(83.346,89.605)
  Bottom Layer w0.5: v2(12.046,58.605) 14.646,61.205 v2(80.246,61.205) ; v2(82.046,65.205) 83.346,66.505 v2(83.346,89.605)
"Input Forward": "Forward Button.2" MCU.23 | length 130.2
  Top Layer w0.5: 8.846,52.805 8.896,52.855 12.096,52.855 v2(12.146,52.905) ; v2(80.246,58.705) 84.546,63.005 v2(84.546,65.305) ; MCU.23@84.746,112.025 84.746,106.554 86,105.3 86,89.859 v2(85.846,89.705)
  Bottom Layer w0.5: v2(12.146,52.905) 18.141,58.9 79.568,58.9 79.616,58.852 80.099,58.852 v2(80.246,58.705) ; v2(84.546,65.305) 84.546,88.405 v2(85.846,89.705)
MISO: "Pmod MicroSD Header.3" MCU.18 | length 51.2
  Top Layer w0.508: MCU.18@97.446,112.025 108.006,122.585 144.306,122.585
MOSI: "Pmod MicroSD Header.2" MCU.17 | length 47.6
  Top Layer w0.508: MCU.17@99.986,112.025 108.006,120.045 144.306,120.045
"NetA1 Cell Reset Decoder_4": "A1 Cell Reset Decoder.4" "A1 Cell Set Decoder.6" "A1 Pin Reset Decoder.4" "A1 Pin Set Decoder.6" MCU.28 | length 114.1
  Top Layer w0.5: 20.741,88.105 20.802,88.165 20.802,98.582 v1(20.849,98.629) ; 38.341,88.105 38.341,98.524 v1@38.346,98.529 ; v1@58.146,98.605 58.181,98.57 58.181,88.105 ; v1@70.046,98.505 70.046,112.88 70.339,113.173 70.898,113.173 MCU.28@72.046,112.025 ; 75.881,88.105 75.915,88.139 75.915,98.496 v1(75.949,98.529)
  Bottom Layer w0.5: v1@20.846,98.605 20.921,98.529 v1(38.349,98.529) v1(70.049,98.529) 75.771,98.529 v1@75.946,98.705
  other v1: 58.15,98.564
"NetA1 Cell Reset Decoder_6": "A1 Cell Reset Decoder.6" "A1 Cell Set Decoder.4" "A1 Pin Reset Decoder.6" "A1 Pin Set Decoder.4" MCU.2 | length 102.3
  Top Layer w0.5: v1(23.249,99.629) 23.265,99.613 23.265,88.121 23.281,88.105 ; v1@40.846,99.605 40.881,99.57 40.881,88.105 ; 55.641,88.105 55.641,99.7 v1@55.646,99.705 ; 73.341,88.105 73.345,88.109 73.345,99.626 v1(73.349,99.629) ; v1@74.586,99.659 MCU.2@74.586,104.405
  Bottom Layer w0.5: v1@23.246,99.605 23.301,99.659 v1(74.609,99.659)
  other v1: 40.849,99.629 55.65,99.664
"NetA1 Cell Reset Decoder_7": "A1 Cell Reset Decoder.7" "A1 Reset Source.8" | length 18.2
  Top Layer w0.5: v2(69.046,78.505) 69.046,78.23 69.536,77.74 69.536,75.405 ; v2(71.246,90.105) 72.071,89.28 72.071,88.105
  Bottom Layer w0.5: v2(69.046,78.505) 69.046,87.905 v2(71.246,90.105)
"NetA1 Cell Reset Decoder_9": "A1 Cell Reset Decoder.9" "A1 Reset Source.7" | length 7.3
  Top Layer w0.5: 70.801,82.705 70.804,82.702 70.804,75.407 70.806,75.405
"NetA1 Cell Reset Decoder_10": "A1 Cell Reset Decoder.10" "A1 Reset Source.6" | length 7.3
  Top Layer w0.5: 72.071,82.705 72.074,82.702 72.074,75.407 72.076,75.405
"NetA1 Cell Reset Decoder_11": "A1 Cell Reset Decoder.11" "A1 Reset Source.5" | length 7.3
  Top Layer w0.5: 73.341,82.705 73.344,82.702 73.344,75.407 73.346,75.405
"NetA1 Cell Reset Decoder_12": "A1 Cell Reset Decoder.12" "A1 Reset Source.4" | length 7.3
  Top Layer w0.5: 74.611,82.705 74.614,82.702 74.614,75.407 74.616,75.405
"NetA1 Cell Reset Decoder_13": "A1 Cell Reset Decoder.13" "A1 Reset Source.3" | length 7.3
  Top Layer w0.5: 75.881,82.705 75.884,82.702 75.884,75.407 75.886,75.405
"NetA1 Cell Reset Decoder_14": "A1 Cell Reset Decoder.14" "A1 Reset Source.2" | length 7.3
  Top Layer w0.5: 77.151,82.705 77.154,82.702 77.154,75.407 77.156,75.405
"NetA1 Cell Reset Decoder_15": "A1 Cell Reset Decoder.15" "A1 Reset Source.1" | length 7.3
  Top Layer w0.5: 78.421,82.705 78.424,82.702 78.424,75.407 78.426,75.405
"NetA1 Cell Set Decoder_7": "A1 Cell Set Decoder.7" "A1 Set Sink.8" | length 19.1
  Top Layer w0.5: v2(33.946,78.805) 33.946,78.548 34.536,77.958 34.536,75.505 ; v2(36.446,90.605) 36.446,90.418 37.071,89.793 37.071,88.105
  Bottom Layer w0.5: v2(33.946,78.805) 33.946,88.105 v2(36.446,90.605)
"NetA1 Cell Set Decoder_9": "A1 Cell Set Decoder.9" "A1 Set Sink.7" | length 7.2
  Top Layer w0.5: 35.801,82.705 35.804,82.702 35.804,75.507 35.806,75.505
"NetA1 Cell Set Decoder_10": "A1 Cell Set Decoder.10" "A1 Set Sink.6" | length 7.2
  Top Layer w0.5: 37.071,82.705 37.074,82.702 37.074,75.507 37.076,75.505
"NetA1 Cell Set Decoder_11": "A1 Cell Set Decoder.11" "A1 Set Sink.5" | length 7.2
  Top Layer w0.5: 38.341,82.705 38.344,82.702 38.344,75.507 38.346,75.505
"NetA1 Cell Set Decoder_12": "A1 Cell Set Decoder.12" "A1 Set Sink.4" | length 7.2
  Top Layer w0.5: 39.611,82.705 39.614,82.702 39.614,75.507 39.616,75.505
"NetA1 Cell Set Decoder_13": "A1 Cell Set Decoder.13" "A1 Set Sink.3" | length 7.2
  Top Layer w0.5: 40.881,82.705 40.884,82.702 40.884,75.507 40.886,75.505
"NetA1 Cell Set Decoder_14": "A1 Cell Set Decoder.14" "A1 Set Sink.2" | length 7.2
  Top Layer w0.5: 42.151,82.705 42.154,82.702 42.154,75.507 42.156,75.505
"NetA1 Cell Set Decoder_15": "A1 Cell Set Decoder.15" "A1 Set Sink.1" | length 7.2
  Top Layer w0.5: 43.421,82.705 43.424,82.702 43.424,75.507 43.426,75.505
"NetA1 Pin Reset Decoder_10": "A1 Pin Reset Decoder.10" "A1 Reset Sink.6" | length 7.3
  Top Layer w0.5: 54.371,82.705 54.371,75.99 54.476,75.885 54.476,75.405
"NetA1 Pin Reset Decoder_11": "A1 Pin Reset Decoder.11" "A1 Reset Sink.5" | length 7.3
  Top Layer w0.5: 55.641,82.705 55.694,82.652 55.694,75.457 55.746,75.405
"NetA1 Pin Reset Decoder_12": "A1 Pin Reset Decoder.12" "A1 Reset Sink.4" | length 7.3
  Top Layer w0.5: 56.911,82.705 56.911,75.99 57.016,75.885 57.016,75.405
"NetA1 Pin Reset Decoder_13": "A1 Pin Reset Decoder.13" "A1 Reset Sink.3" | length 7.3
  Top Layer w0.5: 58.181,82.705 58.234,82.652 58.234,75.457 58.286,75.405
"NetA1 Pin Reset Decoder_14": "A1 Pin Reset Decoder.14" "A1 Reset Sink.2" | length 7.3
  Top Layer w0.5: 59.451,82.705 59.451,75.99 59.556,75.885 59.556,75.405
"NetA1 Pin Reset Decoder_15": "A1 Pin Reset Decoder.15" "A1 Reset Sink.1" | length 7.3
  Top Layer w0.5: 60.721,82.705 60.774,82.652 60.774,75.457 60.826,75.405
"NetA1 Pin Set Decoder_10": "A1 Pin Set Decoder.10" "A1 Set Source.6" | length 7.2
  Top Layer w0.5: 19.471,82.705 19.474,82.702 19.474,75.507 19.476,75.505
"NetA1 Pin Set Decoder_11": "A1 Pin Set Decoder.11" "A1 Set Source.5" | length 7.2
  Top Layer w0.5: 20.741,82.705 20.744,82.702 20.744,75.507 20.746,75.505
"NetA1 Pin Set Decoder_12": "A1 Pin Set Decoder.12" "A1 Set Source.4" | length 7.2
  Top Layer w0.5: 22.011,82.705 22.014,82.702 22.014,75.507 22.016,75.505
"NetA1 Pin Set Decoder_13": "A1 Pin Set Decoder.13" "A1 Set Source.3" | length 7.2
  Top Layer w0.5: 23.281,82.705 23.284,82.702 23.284,75.507 23.286,75.505
"NetA1 Pin Set Decoder_14": "A1 Pin Set Decoder.14" "A1 Set Source.2" | length 7.2
  Top Layer w0.5: 24.551,82.705 24.554,82.702 24.554,75.507 24.556,75.505
"NetA1 Pin Set Decoder_15": "A1 Pin Set Decoder.15" "A1 Set Source.1" | length 7.2
  Top Layer w0.5: 25.821,82.705 25.824,82.702 25.824,75.507 25.826,75.505
NetA1C1_P$1: A1C1.P$1 A1D1C1.3 | length 16.8
  Bottom Layer w0.5: A1D1C1.3@16.735,24.197 16.735,23.016 18.007,21.744 18.007,9.684 ; A1C1.P$1@16.74,8.507 16.84,8.507 18.005,9.672
NetA1C1_P$2: A1C1.P$2 A1C1.P$4 A1C1.P$6 A1C1.P$8 A1C1.P$10 A1C1.P$12 A1D7C1.3 | length 8.4
  Top Layer w0.5: A1C1.P$8@14.2,33.907 A1C1.P$2@14.2,35.177 A1C1.P$4@15.47,35.177 ; A1C1.P$10@15.47,33.907 A1C1.P$4@15.47,35.177 ; A1C1.P$12@16.74,33.907 A1C1.P$6@16.74,35.177 A1C1.P$4@15.47,35.177
  Bottom Layer w0.5: A1C1.P$2@14.2,35.177 14.223,35.2 14.223,37.137 A1D7C1.3@14.246,37.16
NetA1C1_P$3: A1C1.P$3 A1D2C1.3 | length 29
  Bottom Layer w0.5: A1D2C1.3@15.465,29.994 15.465,29.939 15.392,29.866 15.337,29.866 14.676,29.205 13.446,29.205 12.246,28.005 12.246,7.605 12.846,7.005 14.746,7.005 15.313,7.572 15.313,8.35 A1C1.P$3@15.47,8.507
NetA1C1_P$5: A1C1.P$5 A1D3C1.3 | length 16.8
  Bottom Layer w0.5: A1D3C1.3@14.195,24.197 14.195,23.054 12.9,21.759 12.9,9.707 14.1,8.507 A1C1.P$5@14.2,8.507
NetA1C1_P$7: A1C1.P$7 A1D4C1.3 | length 4.4
  Bottom Layer w0.5: A1D4C1.3@16.735,14.197 16.738,14.194 16.738,9.779 A1C1.P$7@16.74,9.777
NetA1C1_P$9: A1C1.P$9 A1D5C1.3 | length 8.4
  Bottom Layer w0.5: A1C1.P$9@15.47,9.777 A1D5C1.3@15.47,18.192
NetA1C1_P$11: A1C1.P$11 A1D6C1.3 | length 4.4
  Bottom Layer w0.5: A1D6C1.3@14.195,14.197 14.198,14.194 14.198,9.779 A1C1.P$11@14.2,9.777
NetA1C2_P$1: A1C2.P$1 A1D1C2.3 | length 16.7
  Bottom Layer w0.5: A1D1C2.3@25.735,24.097 25.735,22.916 27.007,21.644 27.007,9.584 ; A1C2.P$1@25.84,8.407 27.005,9.572
NetA1C2_P$2: A1C2.P$2 A1C2.P$4 A1C2.P$6 A1C2.P$8 A1C2.P$10 A1C2.P$12 A1D7C2.3 | length 8.4
  Top Layer w0.5: A1C2.P$8@23.2,33.907 A1C2.P$2@23.2,35.177 A1C2.P$4@24.47,35.177 ; A1C2.P$10@24.47,33.907 A1C2.P$4@24.47,35.177 ; A1C2.P$12@25.74,33.907 A1C2.P$6@25.74,35.177 A1C2.P$4@24.47,35.177
  Bottom Layer w0.5: A1C2.P$2@23.2,35.177 23.223,35.2 23.223,37.137 A1D7C2.3@23.246,37.16
NetA1C2_P$3: A1C2.P$3 A1D2C2.3 | length 28.4
  Bottom Layer w0.5: A1D2C2.3@24.467,29.806 24.467,29.526 24.046,29.105 22.546,29.105 21.273,27.832 21.273,8.286 22.56,6.999 23.83,6.999 24.47,7.639 A1C2.P$3@24.47,8.307
NetA1C2_P$5: A1C2.P$5 A1D3C2.3 | length 16.7
  Bottom Layer w0.5: A1C2.P$5@23.1,8.407 21.9,9.607 21.9,21.659 23.195,22.954 A1D3C2.3@23.195,24.097
NetA1C2_P$7: A1C2.P$7 A1D4C2.3 | length 4.4
  Bottom Layer w0.5: A1C2.P$7@25.742,9.589 A1D4C2.3@25.742,14.004
NetA1C2_P$9: A1C2.P$9 A1D5C2.3 | length 8.4
  Bottom Layer w0.5: A1C2.P$9@24.47,9.777 A1D5C2.3@24.47,18.192
NetA1C2_P$11: A1C2.P$11 A1D6C2.3 | length 4.4
  Bottom Layer w0.5: A1C2.P$11@23.202,9.589 A1D6C2.3@23.202,14.004
NetA1C3_P$1: A1C3.P$1 A1D1C3.3 | length 16.9
  Bottom Layer w0.5: A1D1C3.3@34.624,24.198 34.624,23.017 36.1,21.541 36.1,9.767 34.84,8.507 A1C3.P$1@34.74,8.507
NetA1C3_P$2: A1C3.P$2 A1C3.P$4 A1C3.P$6 A1C3.P$8 A1C3.P$10 A1C3.P$12 A1D7C3.3 | length 8.4
  Top Layer w0.5: A1C3.P$8@32.2,33.907 A1C3.P$2@32.2,35.177 A1C3.P$4@33.47,35.177 ; A1C3.P$10@33.47,33.907 A1C3.P$4@33.47,35.177 ; A1C3.P$12@34.74,33.907 A1C3.P$6@34.74,35.177 A1C3.P$4@33.47,35.177
  Bottom Layer w0.5: A1C3.P$2@32.2,35.177 32.223,35.2 32.223,37.137 A1D7C3.3@32.246,37.16
NetA1C3_P$3: A1C3.P$3 A1D2C3.3 | length 28.4
  Bottom Layer w0.5: A1D2C3.3@33.467,29.806 32.666,29.005 31.246,29.005 30.146,27.905 30.146,8.413 31.56,6.999 32.83,6.999 33.47,7.639 A1C3.P$3@33.47,8.307
NetA1C3_P$5: A1C3.P$5 A1D3C3.3 | length 16.7
  Bottom Layer w0.5: A1C3.P$5@31.989,8.508 30.835,9.662 30.835,21.806 32.084,23.055 A1D3C3.3@32.084,24.198
NetA1C3_P$7: A1C3.P$7 A1D4C3.3 | length 4.4
  Bottom Layer w0.5: A1C3.P$7@34.742,9.589 A1D4C3.3@34.742,14.004
NetA1C3_P$9: A1C3.P$9 A1D5C3.3 | length 8.4
  Bottom Layer w0.5: A1C3.P$9@33.472,9.589 A1D5C3.3@33.472,18.004
NetA1C3_P$11: A1C3.P$11 A1D6C3.3 | length 4.4
  Bottom Layer w0.5: A1C3.P$11@32.202,9.589 A1D6C3.3@32.202,14.004
NetA1C4_P$1: A1C4.P$1 A1D1C4.3 | length 16.7
  Bottom Layer w0.5: A1D1C4.3@43.735,24.097 43.735,22.916 45.007,21.644 45.007,9.584 ; A1C4.P$1@43.84,8.407 45.005,9.572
